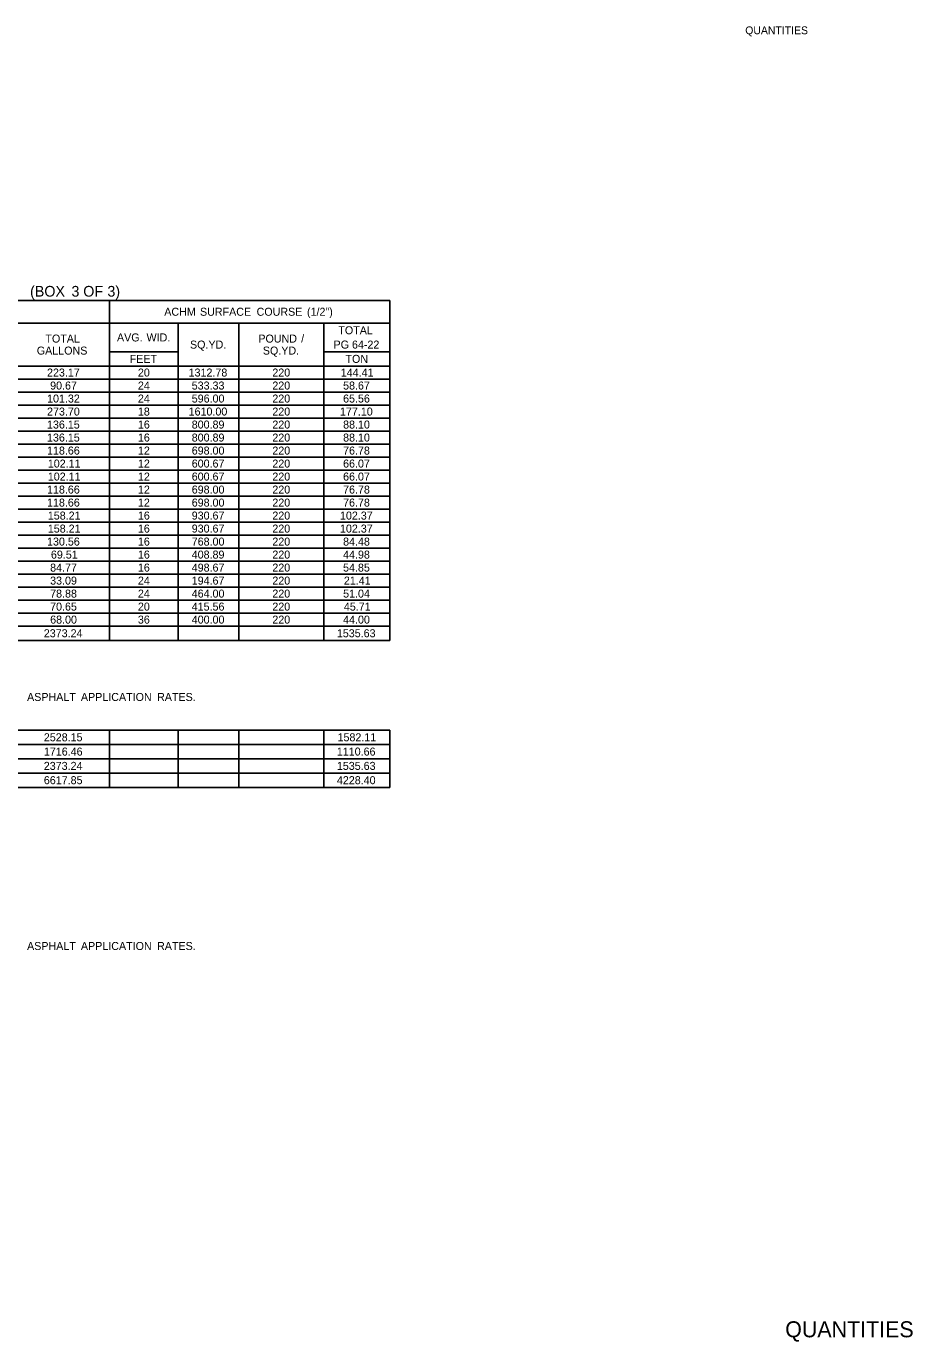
# Model space of a CAD drawing. Extents: x 544250 to 1930787, y -1948365 to 596640.
# Drawn here: x 554624 to 555289, y -1947044 to -1946058 of the extents above; entities that cross this region are included whole.
import ezdxf

# ---------------------------------------------------------------- set-up
doc = ezdxf.new("R2010")
doc.units = 0
for name, color, linetype in [('Default', 7, 'Continuous'), ('R_Border', 7, 'Continuous'), ('R_Border Prem', 7, 'Continuous')]:
    doc.layers.add(name, color=color, linetype=linetype)

msp = doc.modelspace()

# ---------------------------------------------------------------- linework, layer by layer
at = {"layer": 'Default'}
for p, q in [((554100.52, -1946263.45), (554896.61, -1946263.45)), ((554686.49, -1946518.41), (554686.49, -1946263.45)), ((554896.61, -1946518.41), (554896.61, -1946263.45)), ((554511.97, -1946280.51), (554896.61, -1946280.51)), ((554738.17, -1946280.51), (554783.51, -1946280.51)), ((554738.17, -1946518.41), (554738.17, -1946280.51)), ((554783.51, -1946518.41), (554783.51, -1946280.51)), ((554847.37, -1946518.41), (554847.37, -1946280.51)), ((554686.49, -1946301.96), (554738.17, -1946301.96)), ((554686.49, -1946312.69), (554686.49, -1946301.96)), ((554738.17, -1946312.69), (554738.17, -1946301.96)), ((554847.37, -1946301.96), (554896.61, -1946301.96)), ((554100.52, -1946312.69), (554896.61, -1946312.69)), ((554571.44, -1946312.69), (554738.17, -1946312.69)), ((554738.17, -1946312.69), (554896.61, -1946312.69)), ((554100.52, -1946322.44), (554896.61, -1946322.44)), ((554313.07, -1946332.19), (554896.61, -1946332.19)), ((554100.52, -1946341.94), (554896.61, -1946341.94)), ((554100.52, -1946341.94), (554896.61, -1946341.94)), ((554100.52, -1946351.69), (554896.61, -1946351.69)), ((554100.52, -1946351.69), (554896.61, -1946351.69)), ((554100.52, -1946361.44), (554896.61, -1946361.44)), ((554100.52, -1946361.44), (554896.61, -1946361.44)), ((554100.52, -1946371.19), (554896.61, -1946371.19)), ((554100.52, -1946371.19), (554896.61, -1946371.19)), ((554100.52, -1946380.94), (554896.61, -1946380.94)), ((554100.52, -1946380.94), (554896.61, -1946380.94)), ((554100.52, -1946390.69), (554896.61, -1946390.69)), ((554100.52, -1946390.69), (554896.61, -1946390.69)), ((554100.52, -1946400.44), (554896.61, -1946400.44)), ((554100.52, -1946400.44), (554896.61, -1946400.44)), ((554100.52, -1946410.19), (554896.61, -1946410.19)), ((554100.52, -1946410.19), (554896.61, -1946410.19)), ((554100.52, -1946419.94), (554896.61, -1946419.94)), ((554100.52, -1946419.94), (554896.61, -1946419.94)), ((554100.52, -1946429.69), (554896.61, -1946429.69)), ((554100.52, -1946429.69), (554896.61, -1946429.69)), ((554100.52, -1946439.44), (554896.61, -1946439.44)), ((554100.52, -1946439.44), (554896.61, -1946439.44)), ((554100.52, -1946449.19), (554896.61, -1946449.19)), ((554100.52, -1946449.19), (554896.61, -1946449.19)), ((554100.52, -1946458.94), (554896.61, -1946458.94)), ((554100.52, -1946458.94), (554896.61, -1946458.94)), ((554100.52, -1946468.69), (554896.61, -1946468.69)), ((554313.07, -1946478.44), (554896.61, -1946478.44)), ((554313.07, -1946488.19), (554896.61, -1946488.19)), ((554100.52, -1946497.94), (554896.61, -1946497.94)), ((554313.07, -1946497.94), (554896.61, -1946497.94)), ((554100.52, -1946507.69), (554896.61, -1946507.69)), ((554100.52, -1946518.41), (554896.61, -1946518.41)), ((554100.52, -1946585.69), (554896.61, -1946585.69)), ((554686.49, -1946628.59), (554686.49, -1946585.69)), ((554738.17, -1946628.59), (554738.17, -1946585.69)), ((554783.51, -1946628.59), (554783.51, -1946585.69)), ((554847.37, -1946628.59), (554847.37, -1946585.69)), ((554896.61, -1946628.59), (554896.61, -1946585.69)), ((554100.52, -1946596.41), (554896.61, -1946596.41)), ((554100.52, -1946607.14), (554896.61, -1946607.14)), ((554100.52, -1946617.86), (554896.61, -1946617.86)), ((554100.52, -1946628.59), (554896.61, -1946628.59))]:
    msp.add_line(p, q, dxfattribs=at)

# ---------------------------------------------------------------- texts
for s, height, p in [(' (BOX', 8, (554624.06, -1946260.62)), (' 3', 8, (554655.1, -1946260.62)), (' OF', 8, (554663.93, -1946260.62)), (' 3)', 8, (554682.04, -1946260.62)), ('ACHM', 6, (554727.62, -1946274.98)), (' SURFACE', 6, (554752.17, -1946274.98)), (' COURSE', 6, (554794.61, -1946274.98)), (' (1/2")', 6, (554832.39, -1946274.98)), ('TOTAL', 6, (554858.14, -1946288.87)), ('TOTAL', 6, (554638.52, -1946295.1)), ('AVG.', 6, (554692.18, -1946294.24)), (' WID.', 6, (554712.11, -1946294.24)), ('SQ.YD.', 6, (554746.92, -1946299.6)), ('POUND', 6, (554798.17, -1946295.1)), (' /', 6, (554828.04, -1946295.1)), ('PG', 6, (554854.52, -1946299.6)), (' 64-22', 6, (554866.12, -1946299.6)), ('GALLONS', 6, (554632.08, -1946304.1)), ('SQ.YD.', 6, (554801.52, -1946304.1)), ('FEET', 6, (554701.7, -1946310.32)), ('TON', 6, (554863.47, -1946310.32)), ('223.17', 6, (554639.74, -1946320.56)), ('20', 6, (554707.87, -1946320.56)), ('1312.78', 6, (554745.88, -1946320.56)), ('220', 6, (554808.65, -1946320.56)), ('144.41', 6, (554859.94, -1946320.56)), ('90.67', 6, (554642.07, -1946330.31)), ('24', 6, (554707.87, -1946330.31)), ('533.33', 6, (554748.21, -1946330.31)), ('220', 6, (554808.65, -1946330.31)), ('58.67', 6, (554861.69, -1946330.31)), ('101.32', 6, (554639.78, -1946340.06)), ('24', 6, (554707.87, -1946340.06)), ('596.00', 6, (554748.22, -1946340.06)), ('220', 6, (554808.65, -1946340.06)), ('65.56', 6, (554861.69, -1946340.06)), ('273.70', 6, (554639.76, -1946349.81)), ('18', 6, (554707.86, -1946349.81)), ('1610.00', 6, (554745.89, -1946349.81)), ('220', 6, (554808.65, -1946349.81)), ('177.10', 6, (554859.37, -1946349.81)), ('136.15', 6, (554639.72, -1946359.56)), ('16', 6, (554707.86, -1946359.56)), ('800.89', 6, (554748.21, -1946359.56)), ('220', 6, (554808.65, -1946359.56)), ('88.10', 6, (554861.7, -1946359.56)), ('136.15', 6, (554639.72, -1946369.31)), ('118.66', 6, (554639.74, -1946379.06)), ('16', 6, (554707.86, -1946369.31)), ('12', 6, (554707.89, -1946379.06)), ('800.89', 6, (554748.21, -1946369.31)), ('698.00', 6, (554748.22, -1946379.06)), ('220', 6, (554808.65, -1946369.31)), ('220', 6, (554808.65, -1946379.06)), ('88.10', 6, (554861.7, -1946369.31)), ('76.78', 6, (554861.69, -1946379.06)), ('102.11', 6, (554640.33, -1946388.81)), ('12', 6, (554707.89, -1946388.81)), ('600.67', 6, (554748.21, -1946388.81)), ('220', 6, (554808.65, -1946388.81)), ('66.07', 6, (554861.69, -1946388.81)), ('102.11', 6, (554640.33, -1946398.56)), ('12', 6, (554707.89, -1946398.56)), ('600.67', 6, (554748.21, -1946398.56)), ('220', 6, (554808.65, -1946398.56)), ('66.07', 6, (554861.69, -1946398.56)), ('118.66', 6, (554639.74, -1946408.31)), ('12', 6, (554707.89, -1946408.31)), ('698.00', 6, (554748.22, -1946408.31)), ('220', 6, (554808.65, -1946408.31)), ('76.78', 6, (554861.69, -1946408.31)), ('118.66', 6, (554639.74, -1946418.06)), ('12', 6, (554707.89, -1946418.06)), ('698.00', 6, (554748.22, -1946418.06)), ('220', 6, (554808.65, -1946418.06)), ('76.78', 6, (554861.69, -1946418.06)), ('158.21', 6, (554640.33, -1946427.81)), ('16', 6, (554707.86, -1946427.81)), ('930.67', 6, (554748.21, -1946427.81)), ('220', 6, (554808.65, -1946427.81)), ('102.37', 6, (554859.36, -1946427.81)), ('158.21', 6, (554640.33, -1946437.56)), ('16', 6, (554707.86, -1946437.56)), ('930.67', 6, (554748.21, -1946437.56)), ('220', 6, (554808.65, -1946437.56)), ('102.37', 6, (554859.36, -1946437.56)), ('130.56', 6, (554639.74, -1946447.31)), ('16', 6, (554707.86, -1946447.31)), ('768.00', 6, (554748.22, -1946447.31)), ('220', 6, (554808.65, -1946447.31)), ('84.48', 6, (554861.69, -1946447.31)), ('69.51', 6, (554642.66, -1946457.06)), ('16', 6, (554707.86, -1946457.06)), ('408.89', 6, (554748.21, -1946457.06)), ('220', 6, (554808.65, -1946457.06)), ('44.98', 6, (554861.69, -1946457.06)), ('84.77', 6, (554642.07, -1946466.81)), ('16', 6, (554707.86, -1946466.81)), ('498.67', 6, (554748.21, -1946466.81)), ('220', 6, (554808.65, -1946466.81)), ('54.85', 6, (554861.67, -1946466.81)), ('33.09', 6, (554642.07, -1946476.56)), ('24', 6, (554707.87, -1946476.56)), ('194.67', 6, (554748.21, -1946476.56)), ('220', 6, (554808.65, -1946476.56)), ('21.41', 6, (554862.27, -1946476.56)), ('78.88', 6, (554642.07, -1946486.31)), ('24', 6, (554707.87, -1946486.31)), ('464.00', 6, (554748.22, -1946486.31)), ('220', 6, (554808.65, -1946486.31)), ('51.04', 6, (554861.71, -1946486.31)), ('70.65', 6, (554642.05, -1946496.06)), ('20', 6, (554707.87, -1946496.06)), ('415.56', 6, (554748.21, -1946496.06)), ('220', 6, (554808.65, -1946496.06)), ('45.71', 6, (554862.27, -1946496.06)), ('68.00', 6, (554642.09, -1946505.81)), ('36', 6, (554707.86, -1946505.81)), ('400.00', 6, (554748.22, -1946505.81)), ('220', 6, (554808.65, -1946505.81)), ('44.00', 6, (554861.7, -1946505.81)), ('2373.24', 6, (554637.32, -1946516.05)), ('1535.63', 6, (554857.02, -1946516.05)), (' ASPHALT', 6, (554622.55, -1946563.82)), (' APPLICATION', 6, (554662.91, -1946563.82)), (' RATES.', 6, (554720, -1946563.82)), ('2528.15', 6, (554637.35, -1946594.05)), ('1582.11', 6, (554857.52, -1946594.05)), ('1716.46', 6, (554637.37, -1946604.77)), ('1110.66', 6, (554856.99, -1946604.77)), ('2373.24', 6, (554637.32, -1946615.5)), ('1535.63', 6, (554857.02, -1946615.5)), ('6617.85', 6, (554637.35, -1946626.22)), ('4228.40', 6, (554857.05, -1946626.22)), (' ASPHALT', 6, (554622.55, -1946750.54)), (' APPLICATION', 6, (554662.91, -1946750.54)), (' RATES.', 6, (554720, -1946750.54))]:
    msp.add_text(s, height=height, dxfattribs=at).set_placement(p)
at = {"layer": 'R_Border'}
msp.add_text('QUANTITIES', height=12, rotation=360, dxfattribs=at).set_placement((555193.15, -1947040.95))
at = {"layer": 'R_Border Prem'}
msp.add_text('QUANTITIES', height=5.862, rotation=360, dxfattribs=at).set_placement((555163.17, -1946063.9))

doc.saveas('drawing.dxf')
